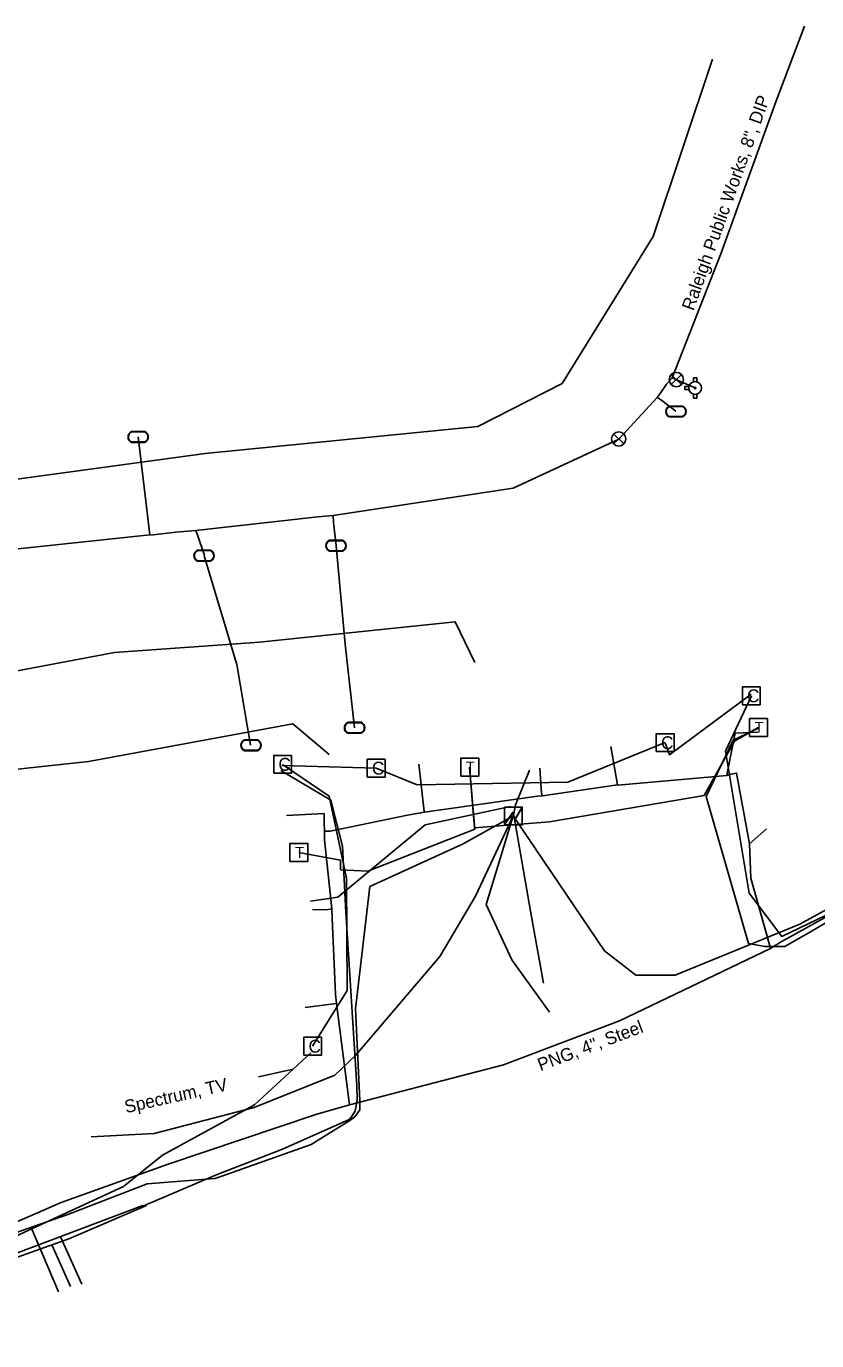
# Model space of a CAD drawing. Extents: x 2070721 to 2083340, y 729290 to 737883.
# Drawn here: x 2080033.2 to 2080279.4, y 734871.6 to 735280.8 of the extents above; entities that cross this region are included whole.
import ezdxf

# ---------------------------------------------------------------- set-up
doc = ezdxf.new("R2010")
doc.units = 0
for name, color, linetype in [('Exist Utilities Gas UG Line SUE LOS B', 7, 'Continuous'), ('Exist Utilities Gas UG Line SUE LOS B Text', 7, 'Continuous'), ('Exist Utilities Power Transformer CELL', 7, 'Continuous'), ('Exist Utilities Power UG Cable SUE LOS B', 7, 'Continuous'), ('Exist Utilities Power UG Cable SUE LOS B Leader', 7, 'Continuous'), ('Exist Utilities Power UG Cable SUE LOS C', 7, 'Continuous'), ('Exist Utilities Telephone Pedestal CELL', 7, 'Continuous'), ('Exist Utilities Telephone UG Cable SUE LOS C', 7, 'Continuous'), ('Exist Utilities TV Pedestal CELL', 7, 'Continuous'), ('Exist Utilities TV UG Cable SUE LOS C', 7, 'Continuous'), ('Exist Utilities TV UG Cable SUE LOS C Leader', 7, 'Continuous'), ('Exist Utilities TV UG Cable SUE LOS C Text', 7, 'Continuous'), ('Exist Utilities Water Fire Hydrant CELL', 7, 'Continuous'), ('Exist Utilities Water Meter CELL', 7, 'Continuous'), ('Exist Utilities Water UG Line SUE LOS B', 7, 'Continuous'), ('Exist Utilities Water UG Line SUE LOS B Text', 7, 'Continuous'), ('Exist Utilities Water Valve CELL', 7, 'Continuous')]:
    doc.layers.add(name, color=color, linetype=linetype)

msp = doc.modelspace()

# ---------------------------------------------------------------- linework, layer by layer
at = {"layer": 'Exist Utilities Gas UG Line SUE LOS B'}
for points in [[(2080265, 734993.65), (2080268.16, 734995.62), (2080315.96, 735022.08), (2080350.22, 735046.21), (2080381.14, 735070.17), (2080396.65, 735089.25), (2080394.64, 735105.68)], [(2080251.38, 735047.5), (2080251.53, 735048.23), (2080253.98, 735060.75), (2080261.09, 735061.09)], [(2080192.42, 735041.08), (2080194, 735041.25), (2080217.37, 735044.63), (2080215.3, 735056.61)], [(2080157.27, 735036.17), (2080157.2, 735036.33), (2080155.44, 735051.07)], [(2080194, 735041.25), (2080193.72, 735042.02), (2080193.14, 735049.84)], [(2080217.46, 735044.57), (2080251.38, 735047.5), (2080252.7, 735047.95)], [(2080252.7, 735047.95), (2080254.46, 735048.32), (2080258.49, 735026.31), (2080263.75, 735030.96)], [(2080157.27, 735036.17), (2080192.42, 735041.08)], [(2080114.31, 735035.09), (2080125.97, 735035.69), (2080126.02, 735032.77), (2080126.13, 735030.24)], [(2080126.13, 735030.24), (2080127.83, 735030.22), (2080151.99, 735035.25), (2080157.27, 735036.17)], [(2080128.42, 735006.06), (2080126.13, 735027.57), (2080126.13, 735030.24)], [(2080258.49, 735026.31), (2080258.94, 735015.59), (2080264.56, 734995.23), (2080265, 734993.65)], [(2080128.42, 735006.06), (2080126.73, 735005.69), (2080122.33, 735005.83)], [(2080129.49, 734979.47), (2080128.65, 735000.62), (2080128.42, 735006.06)], [(2080265, 734993.65), (2080217.97, 734971.17), (2080181.86, 734957.47), (2080133.94, 734945)], [(2080133.94, 734945), (2080133.53, 734948.19), (2080129.81, 734976.57), (2080129.49, 734979.47)], [(2080129.81, 734976.57), (2080128.22, 734976.37), (2080120.05, 734975.34)], [(2079949.32, 734879.97), (2079996.84, 734894.02), (2080044.13, 734914.6), (2080077.42, 734926.53), (2080123.41, 734941.95), (2080133.94, 734945)]]:
    msp.add_lwpolyline(points, dxfattribs=at)
at = {"layer": 'Exist Utilities Power Transformer CELL'}
msp.add_line((2080185, 735035.1), (2080185, 735035.1), dxfattribs=at)
msp.add_lwpolyline([(2080182.15, 735037.71), (2080187.7, 735037.71), (2080187.7, 735032.16), (2080182.15, 735032.16)], close=True, dxfattribs=at)
for points in [[(2080182.15, 735032.16), (2080184.8, 735036.1), (2080185.42, 735033.89), (2080187.7, 735037.71)], [(2080182.22, 735032.16), (2080184.8, 735035.89), (2080185.38, 735033.71), (2080187.7, 735037.56)]]:
    msp.add_lwpolyline(points, dxfattribs=at)
at = {"layer": 'Exist Utilities Power UG Cable SUE LOS B'}
for points in [[(2079821.33, 735124.13), (2079827.86, 735119.63), (2079874.94, 735123.38), (2079958.5, 735131.34), (2080015, 735137.74), (2080088.94, 735147.78), (2080173.89, 735156.26), (2080200.11, 735169.56), (2080228.49, 735215.43), (2080246.93, 735270.61)], [(2079970.93, 735068.94), (2080060.68, 735085.85), (2080105.85, 735089.11), (2080166.83, 735095.38), (2080172.93, 735082.78)], [(2079929, 735034.01), (2079966.1, 735042.55), (2080052.65, 735051.87), (2080116.2, 735063.66), (2080127.54, 735054.13)], [(2080112.49, 735049.08), (2080128.11, 735039.89), (2080131.69, 735025.59), (2080132.72, 735004.97), (2080136.13, 734951), (2080136.32, 734946.38)], [(2080185, 735035.24), (2080185.55, 735038.46), (2080189.91, 735049.2)], [(2080053.4, 734935.01), (2080073.04, 734936.04), (2080104.19, 734944.17), (2080129.31, 734954.23), (2080135.73, 734960.33), (2080162.03, 734991.2), (2080173.15, 735010.03), (2080185, 735035.24)], [(2080184.03, 735037.86), (2080157.46, 735032.17), (2080130.23, 735009.64), (2080121.75, 735008.46)], [(2080185.03, 735035.24), (2080190.32, 735005.32), (2080194.36, 734982.86)], [(2080137.09, 734946.33), (2080135.77, 734974.93), (2080140.28, 735012.96), (2080169.13, 735026.21), (2080185, 735035.04)], [(2080196.17, 734973.88), (2080184.49, 734990.15), (2080176.44, 735007.38), (2080184.91, 735034.97)], [(2079949.54, 734879.56), (2079979.11, 734882.53), (2079996.9, 734893.62), (2080046.16, 734910.81), (2080070.87, 734920.4), (2080091.91, 734922.1), (2080094.14, 734922.76), (2080121.97, 734932.67), (2080134.03, 734940.16), (2080135.53, 734941.3), (2080137.12, 734943.43), (2080137.09, 734946.33)], [(2079987.46, 734894.8), (2080025.82, 734897.12), (2080069.48, 734913.65), (2080069.5, 734913.41), (2080092.72, 734923.35), (2080113.03, 734931.23), (2080133.81, 734940.47), (2080134.5, 734941.28), (2080135.67, 734943.18), (2080136.32, 734946.38)], [(2080070.67, 734913.66), (2080046.49, 734903.28), (2080013.44, 734891.52), (2079979.04, 734880.46), (2079946.47, 734872.13), (2079941.84, 734871.56), (2079937.96, 734876.06)]]:
    msp.add_lwpolyline(points, dxfattribs=at)
at = {"layer": 'Exist Utilities Power UG Cable SUE LOS B Leader'}
for p, q in [((2080034.78, 734906.79), (2080043.22, 734886.76)), ((2080041.28, 734901.2), (2080047.01, 734888.42)), ((2080043.91, 734903.9), (2080050.53, 734889.18))]:
    msp.add_line(p, q, dxfattribs=at)
at = {"layer": 'Exist Utilities Power UG Cable SUE LOS C'}
msp.add_lwpolyline([(2080184.91, 735034.97), (2080213.27, 734992.91), (2080223.08, 734985.41), (2080235.33, 734985.41), (2080274.11, 735001.25), (2080312.76, 735022.46), (2080338.71, 735040.35), (2080379.32, 735071.17)], dxfattribs=at)
at = {"layer": 'Exist Utilities Telephone Pedestal CELL'}
for p, q in [((2080261.2, 735062.55), (2080261.2, 735062.55)), ((2080171.26, 735050.19), (2080171.26, 735050.19)), ((2080118.07, 735023.62), (2080118.07, 735023.62))]:
    msp.add_line(p, q, dxfattribs=at)
for points in [[(2080258.48, 735059.73), (2080264.07, 735059.73), (2080264.07, 735065.32), (2080258.48, 735065.32), (2080258.48, 735059.73)], [(2080168.53, 735047.37), (2080174.13, 735047.37), (2080174.13, 735052.96), (2080168.53, 735052.96), (2080168.53, 735047.37)], [(2080115.35, 735020.79), (2080120.94, 735020.79), (2080120.94, 735026.39), (2080115.35, 735026.39), (2080115.35, 735020.79)]]:
    msp.add_lwpolyline(points, dxfattribs=at)
at = {"layer": 'Exist Utilities Telephone UG Cable SUE LOS C'}
for points in [[(2080258.12, 734995.23), (2080263.29, 734994.32), (2080269.47, 734994.32), (2080277.96, 734999.19), (2080292.29, 735007.6), (2080305.23, 735017.65), (2080343.43, 735047.82), (2080360.16, 735059.94), (2080382.3, 735078.07), (2080399.75, 735092.65), (2080407.82, 735102.46), (2080410.57, 735111.53), (2080417.01, 735135.56), (2080418.86, 735142.51), (2080417.06, 735145.72), (2080413.79, 735150.42), (2080384.27, 735150.47)], [(2080171.24, 735050.15), (2080172.84, 735031.22), (2080196.21, 735033.14), (2080244.31, 735041.32), (2080253.84, 735058.25), (2080261.18, 735062.54)], [(2080258.12, 734995.23), (2080245, 735040.98), (2080253.37, 735058.59), (2080261.28, 735062.28)], [(2080118.09, 735023.61), (2080131.12, 735021.22), (2080131.12, 735018.18), (2080139.57, 735017.81), (2080172.95, 735030.85), (2080171.3, 735050.18)]]:
    msp.add_lwpolyline(points, dxfattribs=at)
at = {"layer": 'Exist Utilities TV Pedestal CELL'}
for p, q in [((2080259.02, 735072.36), (2080259.02, 735072.36)), ((2080232.23, 735057.76), (2080232.23, 735057.76)), ((2080113.05, 735051.03), (2080113.05, 735051.03)), ((2080142.2, 735049.83), (2080142.2, 735049.83)), ((2080122.45, 734963.25), (2080122.45, 734963.25))]:
    msp.add_line(p, q, dxfattribs=at)
for points in [[(2080256.25, 735069.59), (2080261.8, 735069.59), (2080261.8, 735075.14), (2080256.25, 735075.14), (2080256.25, 735069.59)], [(2080229.46, 735054.99), (2080235.01, 735054.99), (2080235.01, 735060.54), (2080229.46, 735060.54), (2080229.46, 735054.99)], [(2080110.28, 735048.26), (2080115.83, 735048.26), (2080115.83, 735053.81), (2080110.28, 735053.81), (2080110.28, 735048.26)], [(2080139.43, 735047.06), (2080144.98, 735047.06), (2080144.98, 735052.61), (2080139.43, 735052.61), (2080139.43, 735047.06)], [(2080119.67, 734960.48), (2080125.22, 734960.48), (2080125.22, 734966.03), (2080119.67, 734966.03), (2080119.67, 734960.48)]]:
    msp.add_lwpolyline(points, dxfattribs=at)
at = {"layer": 'Exist Utilities TV UG Cable SUE LOS C'}
msp.add_line((2080142.28, 735049.86), (2080112.85, 735050.69), dxfattribs=at)
for points in [[(2080259.02, 735072.86), (2080233.57, 735054.03), (2080232.22, 735057.74)], [(2080259.06, 735072.37), (2080251.03, 735055.15), (2080258.34, 735010.88), (2080268.58, 734997.41), (2080290.37, 735007.91), (2080299.29, 735014.42), (2080347.12, 735048.66), (2080359.81, 735057.53)], [(2080142.2, 735049.82), (2080154.93, 735044.6), (2080201.85, 735045.5), (2080232.18, 735057.84)], [(2080122.39, 734963.3), (2080133.14, 734980.6), (2080132.95, 735015.54), (2080127.54, 735041.12), (2080113.06, 735051)], [(2079949.24, 734887.87), (2079959.74, 734898.59), (2079975.94, 734894.45), (2079996.9, 734893.38), (2080024.24, 734901.56), (2080063.46, 734919.58), (2080075.63, 734929.35), (2080104.34, 734945.04), (2080121.88, 734961.24)]]:
    msp.add_lwpolyline(points, dxfattribs=at)
at = {"layer": 'Exist Utilities TV UG Cable SUE LOS C Leader'}
msp.add_line((2080116.31, 734956.12), (2080105.53, 734953.77), dxfattribs=at)
at = {"layer": 'Exist Utilities Water Fire Hydrant CELL'}
msp.add_line((2080241.55, 735168.21), (2080241.55, 735168.21), dxfattribs=at)
for points in [[(2080241.04, 735170.12), (2080241.04, 735171.41), (2080242.07, 735171.41), (2080242.07, 735170.1)], [(2080239.64, 735168.72), (2080238.35, 735168.72), (2080238.35, 735167.7), (2080239.64, 735167.7)], [(2080241.04, 735166.3), (2080241.04, 735165.01), (2080242.07, 735165.01), (2080242.07, 735166.32)]]:
    msp.add_lwpolyline(points, dxfattribs=at)
for radius in [1.98, 0.243]:
    msp.add_circle((2080241.55, 735168.21), radius, dxfattribs=at)
at = {"layer": 'Exist Utilities Water Meter CELL'}
for p, q in [((2080235.56, 735160.9), (2080235.56, 735160.9)), ((2080068.08, 735152.97), (2080068.08, 735152.97)), ((2080129.7, 735119.09), (2080129.7, 735119.09)), ((2080088.6, 735116), (2080088.6, 735116)), ((2080135.46, 735062.41), (2080135.46, 735062.41)), ((2080103.23, 735056.96), (2080103.23, 735056.96))]:
    msp.add_line(p, q, dxfattribs=at)
for points in [[(2080233.53, 735162.6), (2080237.6, 735162.6)], [(2080233.53, 735162.46), (2080237.6, 735162.46)], [(2080237.6, 735159.34), (2080233.5, 735159.34)], [(2080237.6, 735159.2), (2080233.5, 735159.2)], [(2080066.04, 735154.67), (2080070.11, 735154.67)], [(2080066.04, 735154.53), (2080070.11, 735154.53)], [(2080070.11, 735151.41), (2080066.01, 735151.41)], [(2080070.11, 735151.27), (2080066.01, 735151.27)], [(2080086.56, 735117.7), (2080090.63, 735117.7)], [(2080086.56, 735117.56), (2080090.63, 735117.56)], [(2080131.74, 735117.53), (2080127.64, 735117.53)], [(2080131.74, 735117.39), (2080127.64, 735117.39)], [(2080127.66, 735120.79), (2080131.74, 735120.79)], [(2080127.66, 735120.66), (2080131.74, 735120.66)], [(2080090.63, 735114.43), (2080086.53, 735114.43)], [(2080090.63, 735114.3), (2080086.53, 735114.3)], [(2080133.43, 735064.11), (2080137.5, 735064.11)], [(2080133.43, 735063.97), (2080137.5, 735063.97)], [(2080137.5, 735060.84), (2080133.4, 735060.84)], [(2080137.5, 735060.71), (2080133.4, 735060.71)], [(2080101.19, 735058.66), (2080105.27, 735058.66)], [(2080101.19, 735058.52), (2080105.27, 735058.52)], [(2080105.27, 735055.39), (2080101.17, 735055.39)], [(2080105.27, 735055.26), (2080101.17, 735055.26)]]:
    msp.add_lwpolyline(points, dxfattribs=at)
for centre, radius, start, end in [((2080234.26, 735160.89), 1.86, 113.178, 245.9794), ((2080234.27, 735160.89), 1.73, 115.3009, 243.7824), ((2080236.86, 735160.9), 1.86, 293.6483, 66.3084), ((2080236.87, 735160.9), 1.73, 295.1272, 64.8728), ((2080066.77, 735152.96), 1.86, 113.178, 245.9794), ((2080066.78, 735152.96), 1.73, 115.3009, 243.7824), ((2080069.37, 735152.97), 1.86, 293.6483, 66.3084), ((2080069.38, 735152.97), 1.73, 295.1272, 64.8728), ((2080087.29, 735115.99), 1.86, 113.178, 245.9794), ((2080087.3, 735115.99), 1.73, 115.3009, 243.7824), ((2080089.89, 735116), 1.86, 293.6483, 66.3084), ((2080089.9, 735116), 1.73, 295.1272, 64.8728), ((2080128.39, 735119.09), 1.86, 113.178, 245.9794), ((2080128.4, 735119.09), 1.73, 115.3009, 243.7824), ((2080130.99, 735119.09), 1.86, 293.6483, 66.3084), ((2080131, 735119.09), 1.73, 295.1272, 64.8728), ((2080134.16, 735062.4), 1.86, 113.178, 245.9794), ((2080134.17, 735062.4), 1.73, 115.3009, 243.7824), ((2080136.76, 735062.41), 1.86, 293.6483, 66.3084), ((2080136.77, 735062.41), 1.73, 295.1272, 64.8728), ((2080101.92, 735056.95), 1.86, 113.178, 245.9794), ((2080101.93, 735056.95), 1.73, 115.3009, 243.7824), ((2080104.52, 735056.96), 1.86, 293.6483, 66.3084), ((2080104.53, 735056.96), 1.73, 295.1272, 64.8728)]:
    msp.add_arc(centre, radius, start, end, dxfattribs=at)
at = {"layer": 'Exist Utilities Water UG Line SUE LOS B'}
for points in [[(2080234.43, 735171.42), (2080249.6, 735209.95), (2080266.63, 735257.33), (2080275.66, 735280.84)], [(2080229.77, 735165.3), (2080230.67, 735166.49), (2080232.65, 735169.41), (2080234.43, 735171.42)], [(2080234.43, 735171.42), (2080238.14, 735169.72), (2080241.59, 735168.23)], [(2080234.44, 735171.44), (2080234.91, 735171.19)], [(2080128.81, 735128.56), (2080184.91, 735136.98), (2080217.74, 735152.32), (2080229.77, 735165.3)], [(2080229.77, 735165.3), (2080230.71, 735164.59), (2080235.55, 735160.96)], [(2080071.74, 735122.47), (2080071.01, 735128.57), (2080068.07, 735152.99)], [(2080086.04, 735123.83), (2080124.02, 735128.1), (2080128.81, 735128.56)], [(2080128.81, 735128.56), (2080128.91, 735126.35), (2080129.76, 735119.16)], [(2079937.59, 735108.95), (2079940.07, 735109.15), (2079994.44, 735114.29), (2080071.74, 735122.47)], [(2080071.91, 735122.43), (2080079.84, 735123.28), (2080086.04, 735123.83)], [(2080086.04, 735123.83), (2080086.61, 735122.16), (2080088.69, 735116.05)], [(2080135.46, 735062.4), (2080132.54, 735088.49), (2080129.7, 735119.09)], [(2080088.6, 735116), (2080098.77, 735082.1), (2080103.06, 735056.97)]]:
    msp.add_lwpolyline(points, dxfattribs=at)
at = {"layer": 'Exist Utilities Water Valve CELL'}
for points in [[(2080237.25, 735172.42), (2080234.1, 735169.27), (2080235.68, 735170.85), (2080237.25, 735169.27), (2080234.1, 735172.42)], [(2080219.32, 735153.93), (2080216.17, 735150.78), (2080217.75, 735152.35), (2080219.32, 735150.78), (2080216.17, 735153.93)]]:
    msp.add_lwpolyline(points, dxfattribs=at)
for centre in [(2080235.68, 735170.85), (2080217.75, 735152.35)]:
    msp.add_circle(centre, 2.23, dxfattribs=at)

# ---------------------------------------------------------------- texts
at = {"layer": 'Exist Utilities Gas UG Line SUE LOS B Text'}
msp.add_text('PNG, 4", Steel', height=4, rotation=20.7699, dxfattribs=at).set_placement((2080193.39, 734955.43))
at = {"layer": 'Exist Utilities Telephone Pedestal CELL'}
for p in [(2080260.07, 735060.84), (2080170.13, 735048.48), (2080116.94, 735021.91)]:
    msp.add_text('T', height=3.42, dxfattribs=at).set_placement(p)
at = {"layer": 'Exist Utilities TV Pedestal CELL'}
for p in [(2080257.71, 735070.36), (2080230.93, 735055.76), (2080111.75, 735049.03), (2080140.9, 735047.83), (2080121.14, 734961.25)]:
    msp.add_text('C', height=4, dxfattribs=at).set_placement(p)
at = {"layer": 'Exist Utilities TV UG Cable SUE LOS C Text'}
msp.add_text('Spectrum, TV ', height=4, rotation=12.6409, dxfattribs=at).set_placement((2080064.3, 734942.38))
at = {"layer": 'Exist Utilities Water UG Line SUE LOS B Text'}
msp.add_text('Raleigh Public Works, 8", DIP ', height=4, rotation=70.2361, dxfattribs=at).set_placement((2080241.04, 735192.03))

doc.saveas('drawing.dxf')
